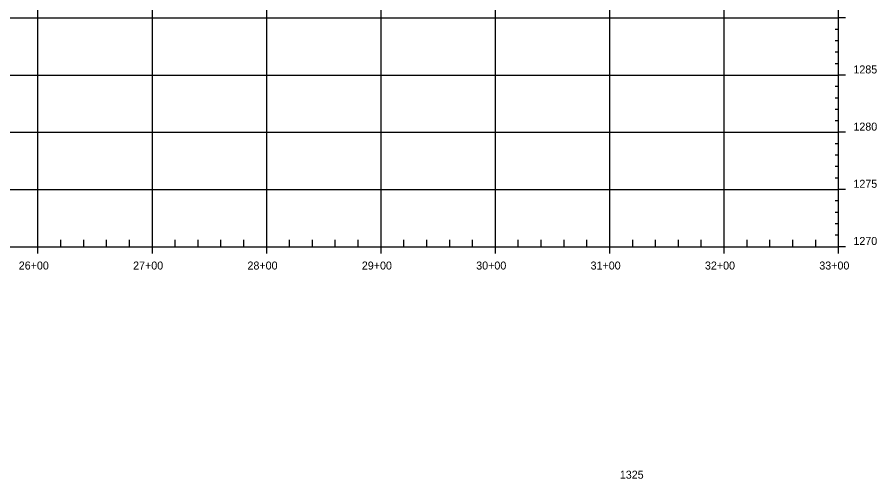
# Model space of a CAD drawing. Extents: x 670877 to 686811, y 705985 to 708501.
# Drawn here: x 686059 to 686811, y 707690 to 708094 of the extents above; entities that cross this region are included whole.
import ezdxf

# ---------------------------------------------------------------- set-up
doc = ezdxf.new("R2010")
doc.units = 0
doc.layers.add('30', color=7, linetype='Continuous')
doc.layers.add('37', color=7, linetype='Continuous')

msp = doc.modelspace()

# ---------------------------------------------------------------- linework, layer by layer
at = {"layer": '37'}
for p, q in [((686077.28, 707892.85), (686077.28, 708492.85)), ((686177.28, 707892.85), (686177.28, 708492.85)), ((686277.28, 707892.85), (686277.28, 708492.85)), ((686377.28, 707892.85), (686377.28, 708492.85)), ((686477.28, 707892.85), (686477.28, 708492.85)), ((686577.28, 707892.85), (686577.28, 708492.85)), ((686677.28, 707892.85), (686677.28, 708492.85)), ((686777.28, 707892.85), (686777.28, 708492.85)), ((684477.28, 708092.85), (686777.28, 708092.85)), ((686783.28, 708092.85), (686777.28, 708092.85)), ((686777.28, 708082.85), (686774.28, 708082.85)), ((686777.28, 708072.85), (686774.28, 708072.85)), ((686777.28, 708062.85), (686774.28, 708062.85)), ((686777.28, 708052.85), (686774.28, 708052.85)), ((684477.28, 708042.85), (686777.28, 708042.85)), ((686783.28, 708042.85), (686777.28, 708042.85)), ((686777.28, 708032.85), (686774.28, 708032.85)), ((686777.28, 708022.85), (686774.28, 708022.85)), ((686777.28, 708012.85), (686774.28, 708012.85)), ((686777.28, 708002.85), (686774.28, 708002.85)), ((684477.28, 707992.85), (686777.28, 707992.85)), ((686783.28, 707992.85), (686777.28, 707992.85)), ((686777.28, 707982.85), (686774.28, 707982.85)), ((686777.28, 707972.85), (686774.28, 707972.85)), ((686777.28, 707962.85), (686774.28, 707962.85)), ((686777.28, 707952.85), (686774.28, 707952.85)), ((684477.28, 707942.85), (686777.28, 707942.85)), ((686783.28, 707942.85), (686777.28, 707942.85)), ((686777.28, 707932.85), (686774.28, 707932.85)), ((686777.28, 707922.85), (686774.28, 707922.85)), ((686777.28, 707912.85), (686774.28, 707912.85)), ((686097.28, 707892.85), (686097.28, 707898.85)), ((686117.28, 707892.85), (686117.28, 707898.85)), ((686137.28, 707892.85), (686137.28, 707898.85)), ((686157.28, 707892.85), (686157.28, 707898.85)), ((686197.28, 707892.85), (686197.28, 707898.85)), ((686217.28, 707892.85), (686217.28, 707898.85)), ((686237.28, 707892.85), (686237.28, 707898.85)), ((686257.28, 707892.85), (686257.28, 707898.85)), ((686297.28, 707892.85), (686297.28, 707898.85)), ((686317.28, 707892.85), (686317.28, 707898.85)), ((686337.28, 707892.85), (686337.28, 707898.85)), ((686357.28, 707892.85), (686357.28, 707898.85)), ((686397.28, 707892.85), (686397.28, 707898.85)), ((686417.28, 707892.85), (686417.28, 707898.85)), ((686437.28, 707892.85), (686437.28, 707898.85)), ((686457.28, 707892.85), (686457.28, 707898.85)), ((686497.28, 707892.85), (686497.28, 707898.85)), ((686517.28, 707892.85), (686517.28, 707898.85)), ((686537.28, 707892.85), (686537.28, 707898.85)), ((686557.28, 707892.85), (686557.28, 707898.85)), ((686597.28, 707892.85), (686597.28, 707898.85)), ((686617.28, 707892.85), (686617.28, 707898.85)), ((686637.28, 707892.85), (686637.28, 707898.85)), ((686657.28, 707892.85), (686657.28, 707898.85)), ((686697.28, 707892.85), (686697.28, 707898.85)), ((686717.28, 707892.85), (686717.28, 707898.85)), ((686737.28, 707892.85), (686737.28, 707898.85)), ((686757.28, 707892.85), (686757.28, 707898.85)), ((686777.28, 707902.85), (686774.28, 707902.85)), ((684477.28, 707892.85), (686777.28, 707892.85)), ((686077.28, 707886.85), (686077.28, 707892.85)), ((686177.28, 707886.85), (686177.28, 707892.85)), ((686277.28, 707886.85), (686277.28, 707892.85)), ((686377.28, 707886.85), (686377.28, 707892.85)), ((686477.28, 707886.85), (686477.28, 707892.85)), ((686577.28, 707886.85), (686577.28, 707892.85)), ((686677.28, 707886.85), (686677.28, 707892.85)), ((686783.28, 707892.85), (686777.28, 707892.85)), ((686777.28, 707886.85), (686777.28, 707892.85))]:
    msp.add_line(p, q, dxfattribs=at)

# ---------------------------------------------------------------- texts
at = {"layer": '30'}
for s, p in [('1285', (686790.28, 708044.35)), ('1280', (686790.28, 707994.35)), ('1275', (686790.28, 707944.35)), ('1270', (686790.28, 707894.35)), ('26+00', (686060.47, 707872.85)), ('27+00', (686160.47, 707872.85)), ('28+00', (686260.47, 707872.85)), ('29+00', (686360.47, 707872.85)), ('30+00', (686460.47, 707872.85)), ('31+00', (686560.47, 707872.85)), ('32+00', (686660.47, 707872.85)), ('33+00', (686760.47, 707872.85)), ('1325', (686586.03, 707689.93))]:
    msp.add_text(s, height=7, dxfattribs=at).set_placement(p)

doc.saveas('drawing.dxf')
